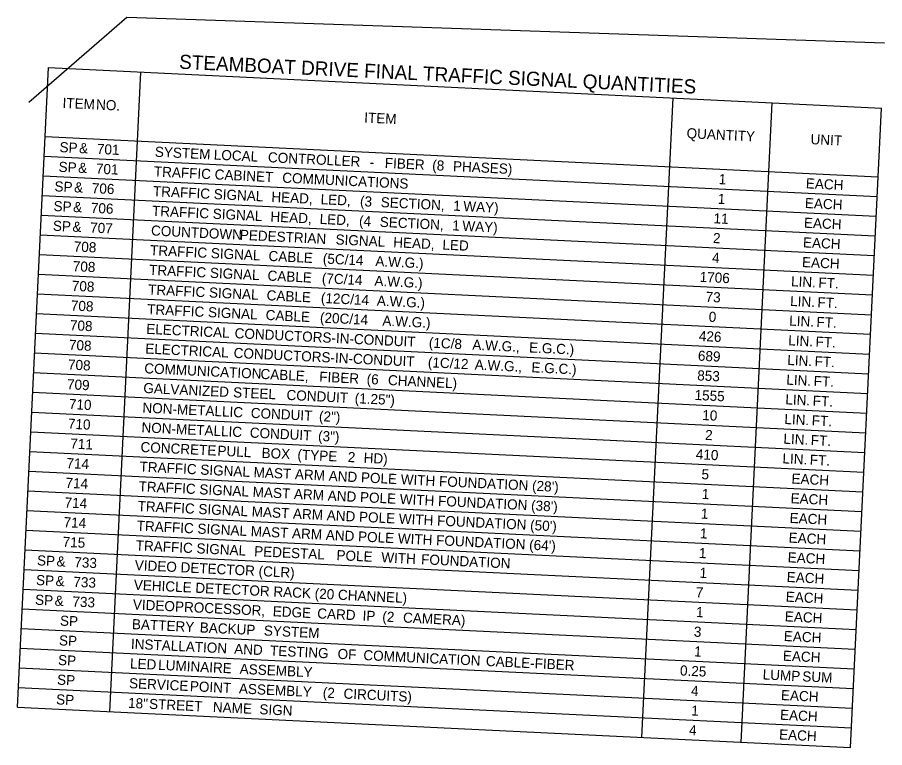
# Model space of a CAD drawing. Extents: x 661018 to 663325, y 642537 to 643074.
# Drawn here: x 661018.2 to 661225.9, y 642622.3 to 642797.3 of the extents above; entities that cross this region are included whole.
import ezdxf

# ---------------------------------------------------------------- set-up
doc = ezdxf.new("R2010")
doc.units = 0
doc.layers.add('R_Border Notes', color=7, linetype='Continuous')
doc.layers.add('R_Proposed Road Annot', color=7, linetype='Continuous')

msp = doc.modelspace()

# ---------------------------------------------------------------- linework, layer by layer
at = {"layer": 'R_Border Notes'}
for p, q in [((661018.23, 642631.95), (661025.67, 642785.25)), ((661025.67, 642785.25), (661225.17, 642775.56)), ((661040.4, 642630.87), (661047.84, 642784.17)), ((661167.8, 642624.68), (661175.24, 642777.99)), ((661191.55, 642623.53), (661198.99, 642776.83)), ((661217.73, 642622.26), (661225.17, 642775.56)), ((661024.87, 642768.74), (661224.37, 642759.05)), ((661024.64, 642764.02), (661224.14, 642754.33)), ((661024.41, 642759.31), (661223.91, 642749.62)), ((661024.18, 642754.59), (661223.68, 642744.9)), ((661023.95, 642749.87), (661223.45, 642740.18)), ((661023.73, 642745.15), (661223.22, 642735.47)), ((661023.5, 642740.44), (661222.99, 642730.75)), ((661023.27, 642735.72), (661222.77, 642726.03)), ((661023.04, 642731), (661222.54, 642721.32)), ((661022.81, 642726.29), (661222.31, 642716.6)), ((661022.58, 642721.57), (661222.08, 642711.88)), ((661022.35, 642716.85), (661221.85, 642707.16)), ((661022.35, 642716.85), (661221.85, 642707.16)), ((661022.12, 642712.14), (661221.62, 642702.45)), ((661021.89, 642707.42), (661221.39, 642697.73)), ((661021.66, 642702.7), (661221.16, 642693.01)), ((661021.44, 642697.98), (661220.93, 642688.3)), ((661021.21, 642693.27), (661220.7, 642683.58)), ((661020.98, 642688.55), (661220.47, 642678.86)), ((661020.75, 642683.83), (661220.25, 642674.15)), ((661020.52, 642679.12), (661220.02, 642669.43)), ((661020.29, 642674.4), (661219.79, 642664.71)), ((661020.06, 642669.68), (661219.56, 642659.99)), ((661019.83, 642664.96), (661219.33, 642655.28)), ((661019.6, 642660.25), (661219.1, 642650.56)), ((661019.37, 642655.53), (661218.87, 642645.84)), ((661019.14, 642650.81), (661218.64, 642641.13)), ((661018.92, 642646.1), (661218.41, 642636.41)), ((661018.69, 642641.38), (661218.18, 642631.69)), ((661018.46, 642636.66), (661217.95, 642626.98)), ((661018.23, 642631.95), (661217.73, 642622.26))]:
    msp.add_line(p, q, dxfattribs=at)
at = {"layer": 'R_Proposed Road Annot'}
msp.add_line((661044.47, 642797.29), (661021, 642776.87), dxfattribs=at)
msp.add_lwpolyline([(661225.92, 642791.08), (661044.47, 642797.29)], dxfattribs=at)

# ---------------------------------------------------------------- texts
at = {"layer": 'R_Border Notes'}
for s, height, p in [('STEAMBOAT DRIVE FINAL TRAFFIC SIGNAL QUANTITIES', 3.3906, (661056.92, 642784.99)), ('ITEM', 2.422, (661029.01, 642775.6)), (' NO.', 2.422, (661036.14, 642775.25)), ('ITEM', 2.422, (661101.25, 642772.09)), ('QUANTITY', 2.422, (661178.45, 642768.34)), ('UNIT', 2.422, (661208.13, 642766.9)), ('SP', 2.422, (661028.29, 642765)), (' &', 2.422, (661032.08, 642764.81)), (' 701', 2.422, (661036.33, 642764.61)), ('SYSTEM', 2.422, (661051.11, 642763.89)), (' LOCAL', 2.422, (661064.33, 642763.25)), (' CONTROLLER', 2.4218, (661077.3, 642762.62)), (' FIBER', 2.422, (661105.28, 642761.26)), (' (8', 2.422, (661116.64, 642760.71)), ('SP', 2.422, (661028.06, 642760.28)), (' &', 2.422, (661031.85, 642760.1)), (' 701', 2.422, (661036.1, 642759.89)), ('TRAFFIC', 2.422, (661050.88, 642759.17)), (' CABINET', 2.422, (661064.54, 642758.51)), (' -', 2.422, (661101.68, 642761.43)), (' PHASES)', 2.422, (661121.61, 642760.47)), (' COMMUNICATIONS', 2.4218, (661080.73, 642757.72)), ('1', 2.42, (661186.14, 642757.33)), ('EACH', 2.422, (661207.01, 642756.32)), ('SP', 2.422, (661027.08, 642755.6)), (' &', 2.422, (661030.87, 642755.42)), (' 706', 2.422, (661035.12, 642755.21)), ('TRAFFIC', 2.422, (661050.66, 642754.45)), (' SIGNAL', 2.422, (661064.31, 642753.79)), (' HEAD,', 2.422, (661078.12, 642753.12)), (' LED,', 2.422, (661089.91, 642752.55)), ('1', 2.42, (661185.91, 642752.61)), ('SP', 2.422, (661026.85, 642750.88)), (' &', 2.422, (661030.64, 642750.7)), (' 706', 2.422, (661034.89, 642750.49)), (' (3', 2.422, (661099.34, 642752.09)), (' SECTION,', 2.422, (661104.31, 642751.85)), (' 1', 2.422, (661121.66, 642751.01)), (' WAY)', 2.422, (661124.08, 642750.89)), ('EACH', 2.422, (661206.78, 642751.6)), ('TRAFFIC', 2.422, (661050.43, 642749.74)), (' SIGNAL', 2.422, (661064.08, 642749.07)), (' HEAD,', 2.422, (661077.89, 642748.4)), ('SP', 2.422, (661026.69, 642746.16)), (' LED,', 2.422, (661089.68, 642747.83)), (' (4', 2.422, (661099.11, 642747.37)), (' SECTION,', 2.422, (661104.08, 642747.13)), (' 1', 2.422, (661121.43, 642746.29)), (' WAY)', 2.422, (661123.85, 642746.17)), ('11', 2.422, (661184.89, 642747.94)), ('EACH', 2.422, (661206.55, 642746.88)), (' &', 2.422, (661030.48, 642745.98)), (' 707', 2.422, (661034.72, 642745.77)), ('COUNTDOWN', 2.422, (661050.2, 642745.02)), (' PEDESTRIAN', 2.4218, (661070.56, 642744.03)), (' SIGNAL', 2.422, (661093.49, 642742.92)), (' HEAD,', 2.422, (661107.3, 642742.25)), ('2', 2.42, (661184.77, 642743.21)), ('EACH', 2.422, (661206.32, 642742.17)), ('708', 2.422, (661031.69, 642741.19)), ('TRAFFIC', 2.422, (661049.97, 642740.3)), (' LED', 2.422, (661119.09, 642741.68)), (' SIGNAL', 2.422, (661063.62, 642739.64)), (' CABLE', 2.422, (661077.43, 642738.97)), (' (5C/14', 2.422, (661090.44, 642738.34)), (' A.W.G.)', 2.422, (661103.03, 642737.73)), ('4', 2.42, (661184.54, 642738.5)), ('708', 2.422, (661031.46, 642736.47)), ('TRAFFIC', 2.422, (661049.74, 642735.59)), ('EACH', 2.422, (661206.09, 642737.45)), (' SIGNAL', 2.422, (661063.4, 642734.92)), (' CABLE', 2.422, (661077.2, 642734.25)), (' (7C/14', 2.422, (661090.21, 642733.62)), ('1706', 2.422, (661181.58, 642733.91)), ('708', 2.422, (661031.23, 642731.76)), (' A.W.G.)', 2.422, (661102.8, 642733.01)), ('LIN.', 2.422, (661203.47, 642732.85)), (' FT.', 2.422, (661209.11, 642732.58)), ('TRAFFIC', 2.422, (661049.51, 642730.87)), (' SIGNAL', 2.422, (661063.17, 642730.21)), (' CABLE', 2.422, (661076.98, 642729.54)), (' (12C/14', 2.422, (661089.98, 642728.9)), (' A.W.G.)', 2.422, (661103.38, 642728.25)), ('73', 2.422, (661183, 642729.12)), ('LIN.', 2.422, (661203.25, 642728.13)), (' FT.', 2.422, (661208.88, 642727.86)), ('708', 2.422, (661031, 642727.04)), ('TRAFFIC', 2.422, (661049.28, 642726.15)), (' SIGNAL', 2.422, (661062.94, 642725.49)), (' CABLE', 2.422, (661076.75, 642724.82)), (' (20C/14', 2.422, (661089.76, 642724.19)), (' A.W.G.)', 2.422, (661104.71, 642723.46)), ('0', 2.42, (661183.75, 642724.35)), ('LIN.', 2.422, (661203.02, 642723.42)), (' FT.', 2.422, (661208.65, 642723.14)), ('708', 2.422, (661030.77, 642722.32)), ('ELECTRICAL', 2.422, (661049.05, 642721.44)), (' CONDUCTORS-IN-CONDUIT', 2.4218, (661069.32, 642720.45)), ('426', 2.422, (661181.39, 642719.74)), ('708', 2.422, (661030.54, 642717.61)), (' (1C/8', 2.422, (661115.83, 642718.19)), (' A.W.G.,', 2.422, (661126.25, 642717.69)), (' E.G.C.)', 2.422, (661139.83, 642717.03)), ('LIN.', 2.422, (661202.79, 642718.7)), (' FT.', 2.422, (661208.43, 642718.42)), ('ELECTRICAL', 2.422, (661048.82, 642716.72)), (' CONDUCTORS-IN-CONDUIT', 2.4218, (661069.09, 642715.73)), ('689', 2.422, (661181.16, 642715.02)), ('708', 2.422, (661030.31, 642712.89)), (' (1C/12', 2.422, (661115.6, 642713.48)), (' A.W.G.,', 2.422, (661126.82, 642712.93)), ('LIN.', 2.422, (661202.56, 642713.98)), (' FT.', 2.422, (661208.2, 642713.71)), ('COMMUNICATION', 2.4218, (661048.59, 642712)), (' CABLE,', 2.422, (661075.51, 642710.69)), (' E.G.C.)', 2.422, (661140.4, 642712.27)), (' FIBER', 2.422, (661089.58, 642710.01)), (' (6', 2.422, (661100.94, 642709.46)), (' CHANNEL)', 2.422, (661106.04, 642709.21)), ('853', 2.422, (661181, 642710.3)), ('LIN.', 2.422, (661202.33, 642709.26)), (' FT.', 2.422, (661207.97, 642708.99)), ('709', 2.422, (661030.07, 642708.17)), ('GALVANIZED', 2.422, (661048.36, 642707.28)), (' STEEL', 2.422, (661068.95, 642706.28)), (' CONDUIT', 2.422, (661081.74, 642705.66)), (' (1.25")', 2.422, (661098.08, 642704.87)), ('1555', 2.422, (661180.37, 642705.6)), ('LIN.', 2.422, (661202.1, 642704.55)), ('710', 2.422, (661030.53, 642703.42)), ('NON-METALLIC', 2.4218, (661048.14, 642702.57)), (' FT.', 2.422, (661207.74, 642704.27)), (' CONDUIT', 2.422, (661073.18, 642701.35)), (' (2")', 2.422, (661089.52, 642700.56)), ('10', 2.422, (661182.2, 642700.79)), ('710', 2.422, (661030.3, 642698.71)), ('LIN.', 2.422, (661201.87, 642699.83)), (' FT.', 2.422, (661207.51, 642699.56)), ('NON-METALLIC', 2.4218, (661047.91, 642697.85)), (' CONDUIT', 2.422, (661072.95, 642696.63)), (' (3")', 2.422, (661089.3, 642695.84)), ('2', 2.42, (661182.88, 642696.02)), ('LIN.', 2.422, (661201.64, 642695.11)), (' FT.', 2.422, (661207.28, 642694.84)), ('711', 2.422, (661030.86, 642693.95)), ('CONCRETE', 2.422, (661047.68, 642693.13)), (' PULL', 2.422, (661065.2, 642692.28)), (' BOX', 2.422, (661075.77, 642691.77)), (' (TYPE', 2.422, (661084.36, 642691.35)), (' 2', 2.422, (661096.42, 642690.77)), (' HD)', 2.422, (661100.21, 642690.58)), ('410', 2.422, (661180.66, 642691.4)), ('LIN.', 2.422, (661201.41, 642690.4)), (' FT.', 2.422, (661207.05, 642690.12)), ('714', 2.422, (661029.95, 642689.27)), ("TRAFFIC SIGNAL MAST ARM AND POLE WITH FOUNDATION (28')", 2.4218, (661047.45, 642688.42)), ('5', 2.42, (661182.02, 642686.61)), ('714', 2.422, (661029.72, 642684.55)), ("TRAFFIC SIGNAL MAST ARM AND POLE WITH FOUNDATION (38')", 2.4218, (661047.22, 642683.7)), ('EACH', 2.422, (661203.57, 642685.56)), ('1', 2.42, (661182.08, 642681.88)), ('714', 2.422, (661029.49, 642679.83)), ('EACH', 2.422, (661203.35, 642680.85)), ("TRAFFIC SIGNAL MAST ARM AND POLE WITH FOUNDATION (50')", 2.4218, (661046.99, 642678.98)), ('1', 2.42, (661181.85, 642677.16)), ('EACH', 2.422, (661203.12, 642676.13)), ('714', 2.422, (661029.26, 642675.12)), ("TRAFFIC SIGNAL MAST ARM AND POLE WITH FOUNDATION (64')", 2.4218, (661046.76, 642674.27)), ('1', 2.42, (661181.62, 642672.44)), ('EACH', 2.422, (661202.89, 642671.41)), ('715', 2.422, (661029.03, 642670.4)), ('TRAFFIC', 2.422, (661046.53, 642669.55)), (' SIGNAL', 2.422, (661060.19, 642668.89)), (' PEDESTAL', 2.422, (661074, 642668.21)), (' POLE', 2.422, (661093.71, 642667.26)), ('1', 2.42, (661181.39, 642667.73)), ('SP', 2.422, (661022.89, 642665.97)), (' &', 2.422, (661026.68, 642665.78)), (' 733', 2.422, (661030.93, 642665.58)), (' WITH', 2.422, (661104.44, 642666.74)), (' FOUNDATION', 2.4218, (661113.98, 642666.27)), ('EACH', 2.422, (661202.66, 642666.69)), ('VIDEO DETECTOR (CLR)', 2.4218, (661046.3, 642664.83)), ('1', 2.42, (661181.56, 642662.99)), ('SP', 2.422, (661022.66, 642661.25)), (' &', 2.422, (661026.45, 642661.07)), (' 733', 2.422, (661030.7, 642660.86)), ('EACH', 2.422, (661202.43, 642661.98)), ('VEHICLE DETECTOR RACK (20 CHANNEL)', 2.4218, (661046.07, 642660.11)), ('7', 2.42, (661180.65, 642658.31)), ('EACH', 2.422, (661202.2, 642657.26)), ('SP', 2.422, (661022.43, 642656.53)), (' &', 2.422, (661026.22, 642656.35)), (' 733', 2.422, (661030.47, 642656.14)), ('VIDEO', 2.422, (661045.84, 642655.4)), (' PROCESSOR,', 2.4218, (661055.04, 642654.95)), (' EDGE', 2.422, (661078.45, 642653.81)), (' CARD', 2.422, (661089.1, 642653.3)), (' IP', 2.422, (661099.96, 642652.77)), (' (2', 2.422, (661104.68, 642652.54)), ('1', 2.42, (661180.7, 642653.58)), ('EACH', 2.422, (661201.97, 642652.54)), ('SP', 2.422, (661028.39, 642651.52)), ('BATTERY', 2.422, (661045.62, 642650.68)), (' CAMERA)', 2.422, (661109.65, 642652.3)), (' BACKUP', 2.422, (661060.97, 642649.93)), (' SYSTEM', 2.422, (661076.32, 642649.19)), ('3', 2.42, (661180.19, 642648.87)), ('SP', 2.422, (661028.16, 642646.8)), ('EACH', 2.422, (661201.74, 642647.83)), ('INSTALLATION', 2.4218, (661045.39, 642645.96)), (' AND', 2.422, (661069.21, 642644.81)), (' TESTING', 2.422, (661077.79, 642644.39)), ('SP', 2.422, (661027.93, 642642.08)), (' OF', 2.422, (661093.98, 642643.6)), (' COMMUNICATION', 2.4218, (661100.15, 642643.3)), ('1', 2.42, (661180.25, 642644.14)), ('EACH', 2.422, (661201.51, 642643.11)), ('LED', 2.422, (661045.16, 642641.25)), (' LUMINAIRE', 2.422, (661051.01, 642640.96)), (' CABLE-FIBER', 2.4218, (661129.48, 642641.88)), (' ASSEMBLY', 2.422, (661070.53, 642640.01)), ('0.25', 2.422, (661176.87, 642639.58)), ('LUMP', 2.422, (661196.67, 642638.62)), (' SUM', 2.422, (661205.26, 642638.2)), ('SP', 2.422, (661027.7, 642637.37)), ('SERVICE', 2.422, (661044.93, 642636.53)), (' POINT', 2.422, (661058.6, 642635.86)), (' ASSEMBLY', 2.422, (661070.34, 642635.3)), (' (2', 2.422, (661090.43, 642634.32)), (' CIRCUITS)', 2.422, (661095.4, 642634.08)), ('4', 2.42, (661179.5, 642634.72)), ('SP', 2.422, (661027.47, 642632.65)), ('18"', 2.422, (661044.7, 642631.81)), ('EACH', 2.422, (661201.05, 642633.68)), (' STREET', 2.422, (661048.83, 642631.61)), (' NAME', 2.422, (661064.11, 642630.87)), (' SIGN', 2.422, (661075.25, 642630.33)), ('1', 2.42, (661179.56, 642629.99)), ('EACH', 2.422, (661200.83, 642628.96)), ('4', 2.42, (661179.04, 642625.29)), ('EACH', 2.422, (661200.6, 642624.24))]:
    msp.add_text(s, height=height, rotation=357.2199, dxfattribs=at).set_placement(p)

doc.saveas('drawing.dxf')
